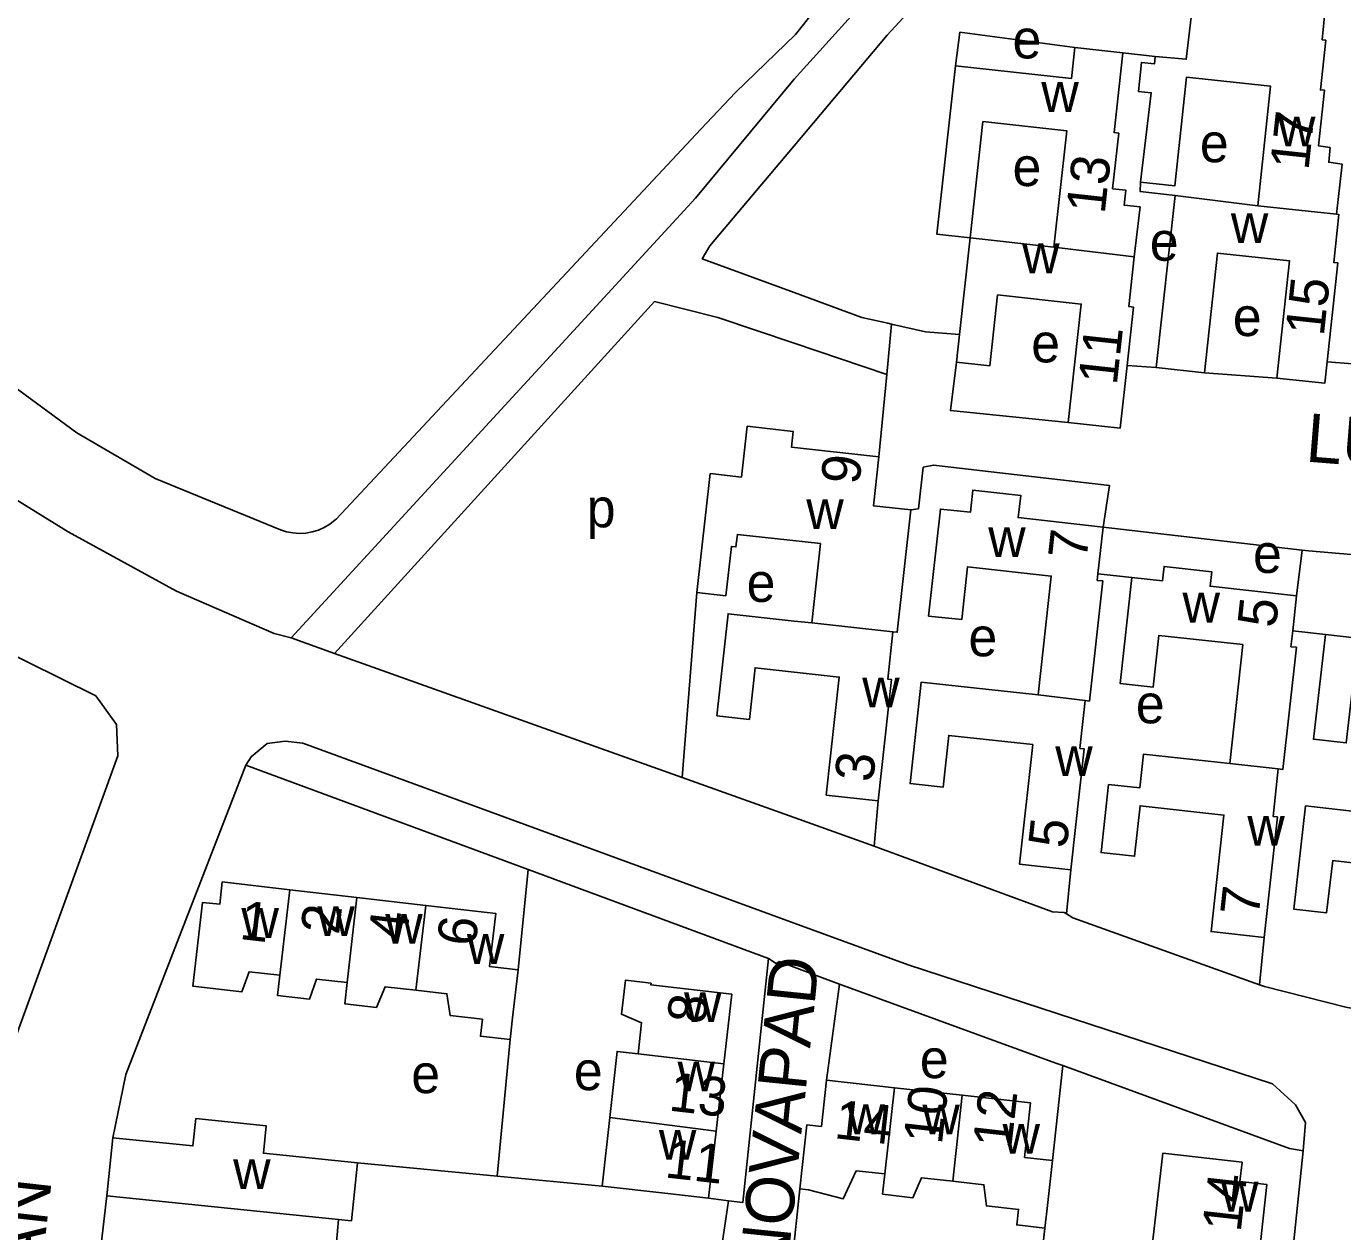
# Model space of a CAD drawing. Extents: x 161936 to 163647, y 386450 to 388633.
# Drawn here: x 162520.7 to 162656.6, y 386585.5 to 386710 of the extents above; entities that cross this region are included whole.
import ezdxf

# ---------------------------------------------------------------- set-up
doc = ezdxf.new("R2010")
doc.units = 0
for name, color, linetype in [('BLT_Basislijn', 7, 'Continuous'), ('BLT_Bebouwing', 7, 'Continuous'), ('BLT_Centroide', 7, 'Continuous'), ('BLT_Huisnummer', 7, 'Continuous'), ('BLT_Huisnummer_ tussenligend', 7, 'Continuous'), ('BLT_Onderverdeling_panden', 7, 'Continuous'), ('BLT_Straatnaam', 7, 'Continuous')]:
    doc.layers.add(name, color=color, linetype=linetype)

msp = doc.modelspace()

# ---------------------------------------------------------------- linework, layer by layer
at = {"layer": 'BLT_Basislijn'}
for p, q in [((162590.38, 386699.41), (162552.77, 386659.15)), ((162610.07, 386679.27), (162609.57, 386674.06)), ((162637.4, 386674.78), (162634.38, 386674.98)), ((162658.1, 386675.11), (162655.04, 386675.38)), ((162609.57, 386674.06), (162608.75, 386665.56)), ((162649.84, 386673.68), (162642.37, 386674.24)), ((162612.86, 386660.18), (162612.05, 386660.09)), ((162652.46, 386655.92), (162631.91, 386658.31)), ((162652.46, 386655.92), (162651.88, 386651.21)), ((162634.88, 386653.08), (162631.38, 386653.48)), ((162588.46, 386632.43), (162589.98, 386651.54)), ((162654.86, 386647.21), (162651.49, 386647.6)), ((162548.1, 386646.87), (162552.57, 386645.25)), ((162588.46, 386632.43), (162552.57, 386645.25)), ((162543.41, 386633.71), (162572.55, 386622.94)), ((162608.26, 386625.34), (162608.69, 386630.03)), ((162572.55, 386622.94), (162571.51, 386612.58)), ((162572.55, 386622.94), (162597.37, 386613.75)), ((162628.59, 386622.9), (162628.13, 386618.35)), ((162648.07, 386611.04), (162648.53, 386615.93)), ((162603.37, 386601.19), (162604.69, 386611.1)), ((162570.68, 386605.38), (162569.37, 386591.28)), ((162627.74, 386602.7), (162626.68, 386592.89)), ((162554.94, 386592.65), (162569.37, 386591.28)), ((162569.37, 386591.28), (162580.18, 386590.25)), ((162529.07, 386589.26), (162528.14, 386581.36)), ((162599.23, 386576.85), (162600.61, 386589.98)), ((162593.25, 386588.73), (162591.17, 386589)), ((162593.25, 386588.73), (162591.5, 386577.15)), ((162552.97, 386586.81), (162552.26, 386578.78)), ((162625.9, 386585.91), (162624.55, 386573.85))]:
    msp.add_line(p, q, dxfattribs=at)
for points in [[(162751.78, 386853.1), (162737.76, 386852.15), (162733.21, 386849.62), (162713.48, 386819.82), (162685.72, 386789.9), (162668.98, 386773.51), (162667.84, 386771.52), (162660.65, 386765.14), (162658.15, 386764.81), (162649.02, 386750.01), (162641.22, 386740.6), (162625.22, 386726.02), (162609.61, 386709.09), (162600, 386697.67), (162591.31, 386687.35), (162590.52, 386686.01), (162600, 386682.53), (162607, 386679.96), (162609.68, 386679.36), (162610.07, 386679.27)], [(162548.1, 386646.87), (162589.82, 386692.28), (162600, 386704.55), (162615.41, 386721.58), (162628.88, 386735.25), (162641.29, 386747.03), (162654.02, 386766.03), (162653.95, 386767.36)], [(162455.71, 386750.58), (162452.51, 386722.52), (162483.88, 386698.28), (162492.52, 386692.46), (162496.84, 386689.07), (162501.53, 386685.32), (162509.05, 386679.68), (162518.81, 386673.29), (162525.95, 386668.03), (162534.03, 386663.33), (162546.98, 386658.02)], [(162627.57, 386739.06), (162612.54, 386723.46), (162605.97, 386716.51), (162600.15, 386709.18), (162593.95, 386703.17), (162590.38, 386699.41)], [(162436.06, 386725.36), (162458.34, 386707.45), (162513.56, 386664.91), (162525.07, 386657.8), (162536.25, 386651.7), (162546.32, 386647.3), (162548.1, 386646.87)], [(162629, 386707.82), (162617.12, 386709.4), (162616.66, 386705.95)], [(162637.28, 386706.9), (162633.94, 386707.28)], [(162639.35, 386692.53), (162635.72, 386692.97), (162635.78, 386693.93)], [(162609.57, 386674.06), (162600, 386677.3), (162592.14, 386679.96), (162585.58, 386681.59), (162552.57, 386645.25)], [(162617.1, 386678.2), (162613.59, 386678.47), (162610.07, 386679.27)], [(162628.31, 386669.11), (162616.14, 386670.33), (162616.79, 386675.35)], [(162631.91, 386658.31), (162632.56, 386662.6), (162614.4, 386664.7), (162613.35, 386664.48), (162612.86, 386660.18)], [(162546.98, 386658.02), (162547.62, 386657.82), (162548.27, 386657.7), (162548.94, 386657.65), (162549.6, 386657.69), (162550.26, 386657.8), (162550.9, 386657.99), (162551.51, 386658.26), (162552.08, 386658.6), (162552.61, 386659.01), (162552.77, 386659.15)], [(162672.99, 386657.9), (162658.66, 386659.3), (162658.42, 386659.23), (162657.84, 386655.74), (162657.53, 386655.47), (162653.1, 386655.84), (162652.46, 386655.92)], [(162507.01, 386652.31), (162517.24, 386646.13), (162527.91, 386640.87), (162530.04, 386637.91), (162530.2, 386634.67), (162518.99, 386603.78), (162516.02, 386592.7), (162515.02, 386587.96)], [(162543.41, 386633.71), (162543.97, 386634.57), (162545.6, 386635.97), (162547.48, 386636.21), (162549.3, 386636), (162600, 386617.41), (162611.78, 386613.09), (162649.4, 386600.8), (162651.77, 386598.64), (162652.81, 386596.82), (162652.58, 386593.9)], [(162529.68, 386595.24), (162531.01, 386601.77), (162543.41, 386633.71)], [(162608.26, 386625.34), (162600, 386628.3), (162588.46, 386632.43)], [(162628.13, 386618.35), (162627.89, 386618.5), (162626.67, 386618.56), (162609.19, 386625), (162608.26, 386625.34)], [(162648.07, 386611.04), (162628.8, 386617.95), (162628.13, 386618.35)], [(162593.25, 386588.73), (162594.7, 386588.55), (162597.37, 386613.75)], [(162604.69, 386611.1), (162602.94, 386611.74), (162600, 386612.85), (162598.46, 386613.44), (162598.16, 386613.23), (162597.37, 386613.75)], [(162627.74, 386602.7), (162627.02, 386602.96), (162604.69, 386611.1)], [(162667.91, 386606.68), (162656.96, 386608.74), (162648.57, 386610.86), (162648.07, 386611.04)], [(162627.74, 386602.7), (162651.17, 386594.14), (162652.58, 386593.9)], [(162648.67, 386556.14), (162648.69, 386556.33), (162652.58, 386593.9)]]:
    msp.add_lwpolyline(points, dxfattribs=at)
at = {"layer": 'BLT_Bebouwing'}
for p, q in [((162654.83, 386711.78), (162654.53, 386708.61)), ((162637.4, 386674.78), (162639.35, 386692.53)), ((162639.35, 386692.53), (162647.87, 386691.49)), ((162618.19, 386688.17), (162617.1, 386678.2)), ((162626.84, 386687.22), (162618.19, 386688.17)), ((162617.1, 386678.2), (162616.79, 386675.35)), ((162631.38, 386653.48), (162631.91, 386658.31)), ((162651.49, 386647.6), (162651.88, 386651.21)), ((162554.88, 386620.06), (162547.95, 386620.86)), ((162561.98, 386619.24), (162554.88, 386620.06)), ((162592.76, 386602.88), (162591.96, 386595.93)), ((162603.37, 386601.19), (162610.37, 386600.41)), ((162610.37, 386600.41), (162617.37, 386599.63)), ((162591.96, 386595.93), (162591.17, 386589)), ((162529.07, 386589.26), (162529.68, 386595.24)), ((162552.97, 386586.81), (162529.07, 386589.26))]:
    msp.add_line(p, q, dxfattribs=at)
for points in [[(162637.28, 386706.9), (162640.5, 386706.62), (162641.26, 386713.29)], [(162654.53, 386708.61), (162654.89, 386708.57), (162654.34, 386703.45), (162654.77, 386703.41), (162654.16, 386697.66), (162655.35, 386697.49), (162655.2, 386695.98), (162656.59, 386695.79), (162656.02, 386690.6)], [(162629, 386707.82), (162628.66, 386704.64), (162616.66, 386705.95)], [(162633.94, 386707.28), (162629, 386707.82)], [(162635.12, 386686.2), (162635.72, 386691.36), (162634.09, 386691.53), (162634.26, 386693.09), (162632.89, 386693.24), (162633.52, 386698.98), (162633.04, 386699.04), (162633.94, 386707.28)], [(162616.66, 386705.95), (162614.75, 386688.55), (162618.19, 386688.17)], [(162635.78, 386693.93), (162636.88, 386703.16), (162635.55, 386703.3), (162635.87, 386706.28), (162637.2, 386706.14), (162637.28, 386706.9)], [(162647.87, 386691.49), (162649.19, 386703.85), (162640.52, 386704.78), (162639.31, 386693.53), (162635.78, 386693.93)], [(162618.19, 386688.17), (162619.51, 386700.18), (162628.16, 386699.23), (162626.84, 386687.22)], [(162656.02, 386690.6), (162656.26, 386690.57), (162655.73, 386685.63), (162656.13, 386685.59), (162655.04, 386675.38)], [(162634.38, 386674.98), (162635.04, 386681.03), (162634.56, 386681.09), (162635.12, 386686.2)], [(162649.84, 386673.68), (162651.14, 386685.8), (162643.71, 386686.6), (162642.37, 386674.24)], [(162616.79, 386675.35), (162620.22, 386674.97), (162621.02, 386682.27), (162629.65, 386681.33), (162628.31, 386669.11)], [(162628.31, 386669.11), (162633.67, 386668.52), (162634.38, 386674.98)], [(162642.37, 386674.24), (162637.4, 386674.78)], [(162655.04, 386675.38), (162654.8, 386673.15), (162649.84, 386673.68)], [(162608.75, 386665.56), (162599.74, 386666.56), (162599.93, 386668.16), (162595.17, 386668.71), (162594.57, 386663.46), (162591.35, 386663.82), (162589.98, 386651.54)], [(162612.05, 386660.09), (162608.19, 386660.51), (162608.75, 386665.56)], [(162631.91, 386658.31), (162623.14, 386659.28), (162623.4, 386661.57), (162618.46, 386662.11), (162618.21, 386659.83), (162615.12, 386660.17), (162613.9, 386649.12), (162617.31, 386648.75), (162617.91, 386654.19), (162626.55, 386653.24), (162625.2, 386640.97)], [(162610.21, 386647.49), (162610.65, 386647.44), (162612.05, 386660.09)], [(162589.98, 386651.54), (162592.96, 386651.21), (162593.53, 386656.31), (162594.01, 386656.25), (162594.16, 386657.54), (162599.56, 386656.95), (162602.73, 386656.6)], [(162602.73, 386656.6), (162601.83, 386648.4)], [(162651.88, 386651.21), (162642.95, 386652.19), (162643.12, 386653.69), (162638.2, 386654.24), (162638.03, 386652.74), (162634.88, 386653.08)], [(162630.05, 386640.38), (162630.5, 386640.33), (162631.87, 386652.74), (162631.3, 386652.8), (162631.38, 386653.48)], [(162634.88, 386653.08), (162633.68, 386642.15), (162637.09, 386641.78), (162637.67, 386647.12), (162646.33, 386646.17), (162644.98, 386633.89)], [(162601.83, 386648.4), (162600, 386648.6), (162593.2, 386649.35), (162592.04, 386638.82), (162595.4, 386638.45), (162595.98, 386643.77), (162600, 386643.33), (162604.67, 386642.82), (162603.33, 386630.62), (162608.69, 386630.03)], [(162672.04, 386648.34), (162666.13, 386649.02), (162665.78, 386645.96), (162654.86, 386647.21)], [(162608.69, 386630.03), (162610.07, 386642.56), (162609.67, 386642.61), (162610.21, 386647.49)], [(162650, 386633.33), (162650.47, 386633.28), (162651.86, 386645.89), (162651.3, 386645.95), (162651.49, 386647.6)], [(162654.86, 386647.21), (162653.62, 386636.4), (162657.01, 386636.01), (162657.63, 386641.37), (162666.26, 386640.38), (162664.85, 386628.15)], [(162625.2, 386640.97), (162613.14, 386642.3), (162611.98, 386631.81), (162615.39, 386631.44), (162615.98, 386636.79), (162624.65, 386635.84), (162623.29, 386623.49), (162628.59, 386622.9)], [(162628.59, 386622.9), (162629.96, 386635.4), (162629.51, 386635.45), (162630.05, 386640.38)], [(162644.98, 386633.89), (162636.09, 386634.87), (162635.7, 386631.36), (162632.48, 386631.71), (162631.71, 386624.69), (162635.16, 386624.31), (162635.73, 386629.52), (162644.39, 386628.57), (162643.06, 386616.53), (162648.53, 386615.93)], [(162648.53, 386615.93), (162649.9, 386628.37), (162649.46, 386628.42), (162650, 386633.33)], [(162664.85, 386628.15), (162652.82, 386629.53), (162651.6, 386618.86), (162654.99, 386618.47), (162655.61, 386623.86), (162664.32, 386622.85), (162662.91, 386610.62), (162668.16, 386610.02)], [(162546.93, 386612.03), (162543.75, 386612.39), (162542.98, 386610.3), (162537.95, 386610.88), (162538.95, 386619.55), (162540.72, 386619.35), (162540.98, 386621.66), (162547.95, 386620.86)], [(162571.51, 386612.58), (162568.58, 386612.92), (162569.21, 386618.41), (162561.98, 386619.24)], [(162570.68, 386605.38), (162570.94, 386607.61), (162571.51, 386612.58)], [(162546.93, 386612.03), (162546.69, 386609.92), (162549.98, 386609.54), (162550.69, 386611.63), (162553.87, 386611.27)], [(162553.87, 386611.27), (162553.62, 386609.08), (162556.89, 386608.71), (162557.78, 386610.84), (162560.97, 386610.48)], [(162583.91, 386603.9), (162584.27, 386607.1), (162582.18, 386607.99), (162582.59, 386611.51), (162585.25, 386611.2), (162585.23, 386611.02), (162593.58, 386610.06), (162592.76, 386602.88)], [(162560.97, 386610.48), (162564.16, 386610.11), (162564.51, 386607.86), (162567.83, 386607.48), (162567.63, 386605.73), (162570.68, 386605.38)], [(162580.97, 386597.32), (162581.73, 386604.15), (162583.91, 386603.9)], [(162600.61, 386589.98), (162601.34, 386596.59), (162602.83, 386596.42), (162603.37, 386601.19)], [(162617.37, 386599.63), (162624.43, 386598.84), (162623.8, 386593.22), (162626.68, 386592.89)], [(162529.68, 386595.24), (162537.95, 386594.4), (162538.24, 386597.22), (162545.52, 386596.47), (162545.23, 386593.65), (162554.94, 386592.65)], [(162580.18, 386590.25), (162580.97, 386597.32)], [(162648.04, 386583.45), (162648.81, 386590.41), (162646.02, 386590.71), (162646.28, 386592.72), (162638.08, 386593.64), (162637.06, 386584.68)], [(162554.94, 386592.65), (162554.83, 386591.64), (162554.32, 386586.67), (162552.97, 386586.81)], [(162609.38, 386591.51), (162606.43, 386591.84), (162605.09, 386588.94), (162601.5, 386589.88), (162600.61, 386589.98)], [(162625.9, 386585.91), (162626.13, 386587.93), (162626.68, 386592.89)], [(162609.38, 386591.51), (162609.14, 386589.4), (162612.28, 386589.05), (162613.16, 386591.11), (162616.38, 386590.75)], [(162616.38, 386590.75), (162619.6, 386590.39), (162619.87, 386588.21), (162623.18, 386587.84), (162623, 386586.24), (162625.9, 386585.91)], [(162591.17, 386589), (162586.68, 386589.51), (162580.18, 386590.25)]]:
    msp.add_lwpolyline(points, dxfattribs=at)
at = {"layer": 'BLT_Onderverdeling_panden'}
for p, q in [((162647.87, 386691.49), (162656.02, 386690.6)), ((162626.84, 386687.22), (162635.12, 386686.2)), ((162601.83, 386648.4), (162610.21, 386647.49)), ((162625.2, 386640.97), (162630.05, 386640.38)), ((162644.98, 386633.89), (162650, 386633.33)), ((162546.93, 386612.03), (162547.95, 386620.86)), ((162553.87, 386611.27), (162554.88, 386620.06)), ((162560.97, 386610.48), (162561.98, 386619.24)), ((162583.91, 386603.9), (162592.76, 386602.88)), ((162609.38, 386591.51), (162610.37, 386600.41)), ((162616.38, 386590.75), (162617.37, 386599.63)), ((162580.97, 386597.32), (162591.96, 386595.93))]:
    msp.add_line(p, q, dxfattribs=at)

# ---------------------------------------------------------------- texts
at = {"layer": 'BLT_Centroide'}
for s, p in [('e', (162622.56, 386706.7)), ('w', (162625.53, 386701.18)), ('w', (162649.97, 386697.62)), ('e', (162641.9, 386695.98)), ('e', (162622.56, 386693.52)), ('w', (162645.1, 386687.64)), ('e', (162636.73, 386685.81)), ('w', (162623.55, 386684.52)), ('e', (162645.3, 386678.03)), ('e', (162624.49, 386675.31)), ('p', (162578.6, 386658.28)), ('w', (162601.27, 386658.09)), ('w', (162620.05, 386655.21)), ('e', (162647.39, 386653.57)), ('e', (162595.11, 386650.58)), ('w', (162640.11, 386648.45)), ('e', (162618.01, 386644.96)), ('w', (162607.04, 386639.69)), ('e', (162635.29, 386638.04)), ('w', (162626.97, 386632.59)), ('w', (162646.8, 386625.41)), ('w', (162542.95, 386615.88)), ('w', (162550.78, 386616.08)), ('w', (162557.8, 386615.28)), ('w', (162566.23, 386613.2)), ('w', (162588.65, 386607.19)), ('e', (162612.99, 386601.4)), ('e', (162560.49, 386599.85)), ('e', (162577.27, 386600.16)), ('w', (162587.98, 386600.03)), ('w', (162605.48, 386595.61)), ('w', (162613.25, 386595.59)), ('w', (162586.05, 386592.97)), ('w', (162621.53, 386593.59)), ('w', (162542.1, 386589.94)), ('w', (162644.09, 386587.62))]:
    msp.add_text(s, height=4, dxfattribs=at).set_placement(p)
at = {"layer": 'BLT_Huisnummer'}
for s, rotation, p in [('17', 83.8822, (162653.11, 386695.08)), ('13', 83.7401, (162632.07, 386690.56)), ('15', 83.8817, (162654.69, 386677.95)), ('11', 83.7442, (162633.32, 386672.89)), ('9', 83.7183, (162606.73, 386662.6)), ('7', 83.7077, (162630.19, 386654.85)), ('5', 83.7112, (162649.74, 386647.82)), ('3', 83.7217, (162608.15, 386631.88)), ('5', 83.7162, (162628.14, 386625.05)), ('7', 83.7154, (162647.96, 386618.02)), ('1', 353.431, (162542.67, 386615.78)), ('2', 83.444, (162553.02, 386616.14)), ('4', 83.444, (162560.01, 386615.48)), ('6', 83.4438, (162567.11, 386614.92)), ('8', 83.4646, (162590.84, 386606.89)), ('13', 353.4655, (162586.98, 386598.06)), ('12', 83.6274, (162622.42, 386594.05)), ('14', 353.6344, (162604.07, 386595.21)), ('11', 353.469, (162586.58, 386591.16)), ('14', 83.6181, (162646.11, 386585.42))]:
    msp.add_text(s, height=4, rotation=rotation, dxfattribs=at).set_placement(p)
at = {"layer": 'BLT_Huisnummer_ tussenligend'}
msp.add_text('10', height=4, rotation=83.6251, dxfattribs=at).set_placement((162615.26, 386594.47))
at = {"layer": 'BLT_Straatnaam'}
for s, rotation, p in [('LUYTELAER', 355.4027, (162652.73, 386665.08)), ('NOVAPAD', 84.1413, (162599.27, 386581.16)), ('PERSEUSLAAN', 83.6124, (162517.87, 386541.7))]:
    msp.add_text(s, height=5, rotation=rotation, dxfattribs=at).set_placement(p)

doc.saveas('drawing.dxf')
